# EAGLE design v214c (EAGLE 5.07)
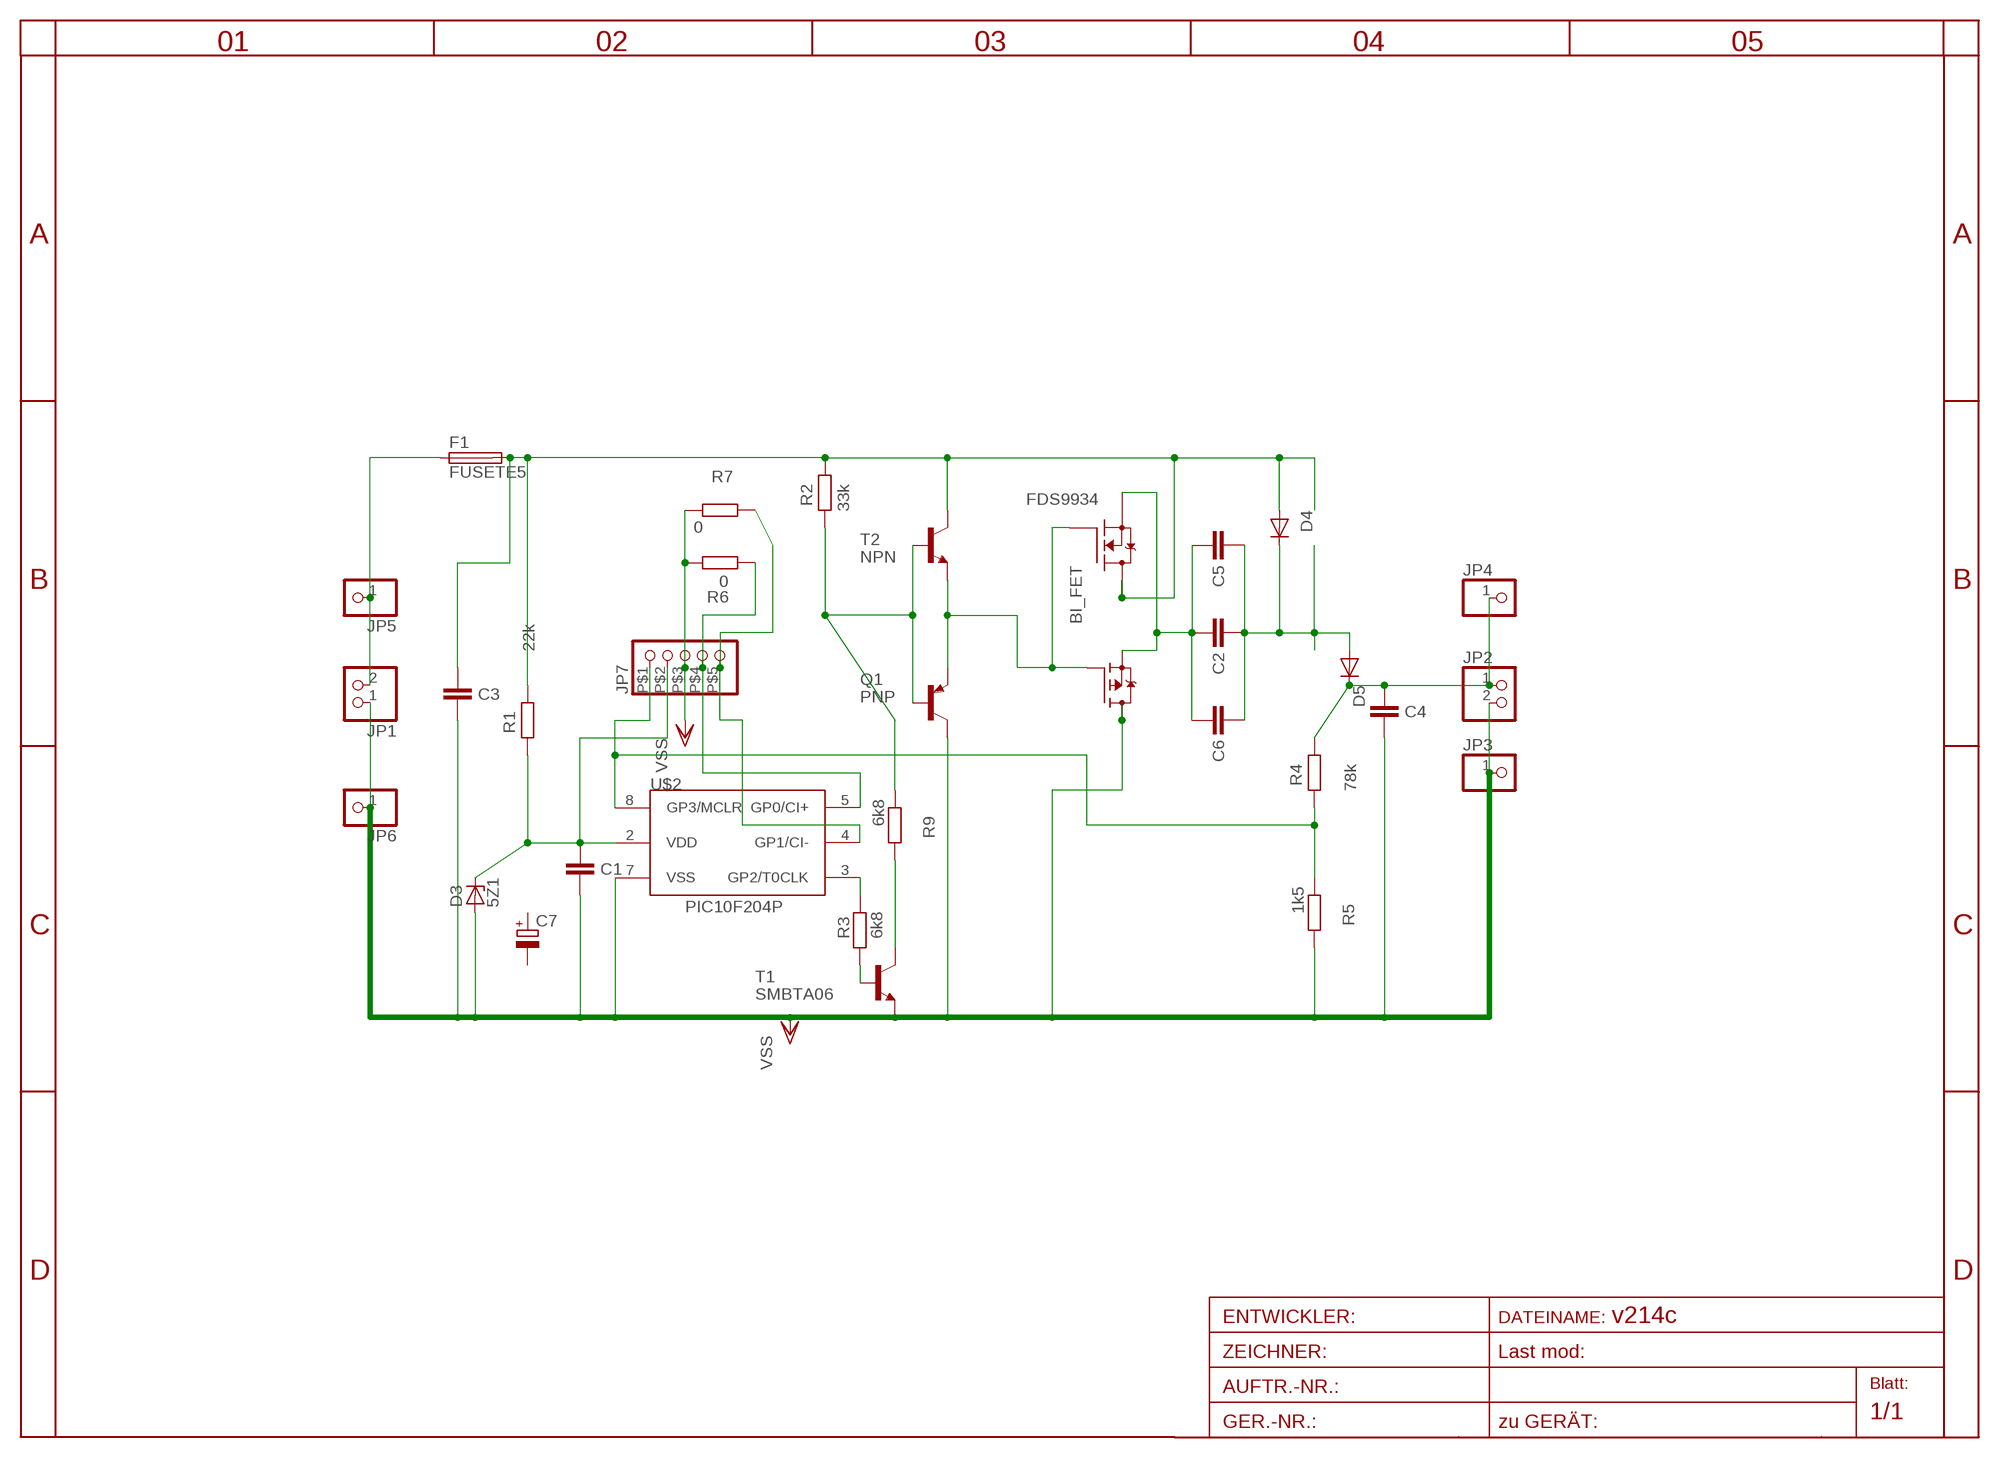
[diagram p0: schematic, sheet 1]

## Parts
BI_FET  FDS9934  [SO-8]
C1  1u  C-EUC1206  [C1206]
C2  10n  C-EUC1206  [C1206]
C3  10n  C-EU050-075X075  [C050-075X075]
C4  10n  C-EU050-075X075  [C050-075X075]
C5  10n  C-EU050-025X075  [C050-025X075]
C6  10n  C-EUC1206  [C1206]
C7  CPOL-EUSMCA  [SMC_A]
D3  5Z1  ZENER-DIODESOD80C  [SOD80C]
D4  DIODE-SMC  [SMC]
D5  DIODE-SMC  [SMC]
F1  FUSETE5  [TE5]
JP1  PINHD-1X2  [1X02X05]
JP2  PINHD-1X2  [1X02X05]
JP3  PINHD-1X11MM6  [1X1MM8]
JP4  PINHD-1X11MM6  [1X1MM8]
JP5  PINHD-1X11MM6  [1X1MM8]
JP6  PINHD-1X11MM6  [1X1MM8]
JP7  PINHD-1X5  [1X05SMD]
Q1  PNP  BC857ASMD  [SOT23-BEC]
R1  22k  R-EU_R1206  [R1206]
R2  33k  R-EU_R1206  [R1206]
R3  6k8  R-EU_R1206  [R1206]
R4  78k  R-EU_R2010  [R2010]
R5  1k5  R-EU_R1206  [R1206]
R6  0  R-EU_R0402  [R0402]
R7  0  R-EU_R0402  [R0402]
R9  6k8  R-EU_R1206  [R1206]
T1  SMBTA06  BC846  [SOT23]
T2  NPN  BC846  [SOT23]
U$2  PIC10F204P  [DIL8]

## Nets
GG: BI_FET.2(Q1G) BI_FET.4(Q2G) Q1.E T2.2(E)
N$1: C1.2 D3.C JP7.P$2 R1.2 U$2.2(VDD)
N$2: R9.2 T1.3(C)
N$3: R3.2 U$2.3(GP2/T0CLK)
N$4: R3.1 T1.1(B)
N$5: JP7.P$1 R4.2 R5.1 U$2.8(GP3/MCLR)
N$6: Q1.B R2.2 R9.1 T2.1(B)
N$7: JP7.P$4 R6.1 U$2.5(GP0/CI+)
N$8: JP7.P$5 R7.2 U$2.4(GP1/CI-)
SS: BI_FET.1(Q1S) BI_FET.3(Q2S) C2.1 C5.1 C6.1
V+IN: F1.1 JP1.2 JP5.1
VFUSE: BI_FET.7(Q1D2) BI_FET.8(Q1D1) C3.2 D4.A F1.2 R1.1 R2.1 T2.3(C)
VMID: C2.2 C5.2 C6.2 D4.C D5.A
VOUT: C4.2 D5.C JP2.1 JP4.1 R4.1
VSS: BI_FET.5(Q2D2) BI_FET.6(Q2D) C1.1 C3.1 C4.1 D3.A JP1.1 JP2.2 JP3.1 JP6.1 JP7.P$3 Q1.C R5.2 R6.2 R7.1 T1.2(E) U$2.7(VSS)
Unconnected: C7.+ C7.-

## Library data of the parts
BI_FET = transistor-fet:FDS9934
C1-C6 = rcl-2:C-EU: CAPACITOR, European symbol
C7 = rcl:CPOL-EU: POLARIZED CAPACITOR, European symbol
D3 = diode-1:ZENER-DIODE: Z-Diode
D4 D5 = diode-1:DIODE-: DIODE
F1 = fuse:FUSE: Fuse
JP1 JP2 = pinhead:PINHD-1X2: PIN HEADER
JP3-JP6 = pinhead:PINHD-1X1: PIN HEADER
JP7 = pinhead:PINHD-1X5: PIN HEADER
Q1 = transistor-pnp:BC857*: PNP Transistror
R1-R7 R9 = rcl-2:R-EU_: RESISTOR, European symbol
T1 T2 = transistor:BC846: NPN TRANSISTOR
U$2 = microchip-5:PIC10F2*: uPC nW 0,25/0,5k Program Flash memory Comparator

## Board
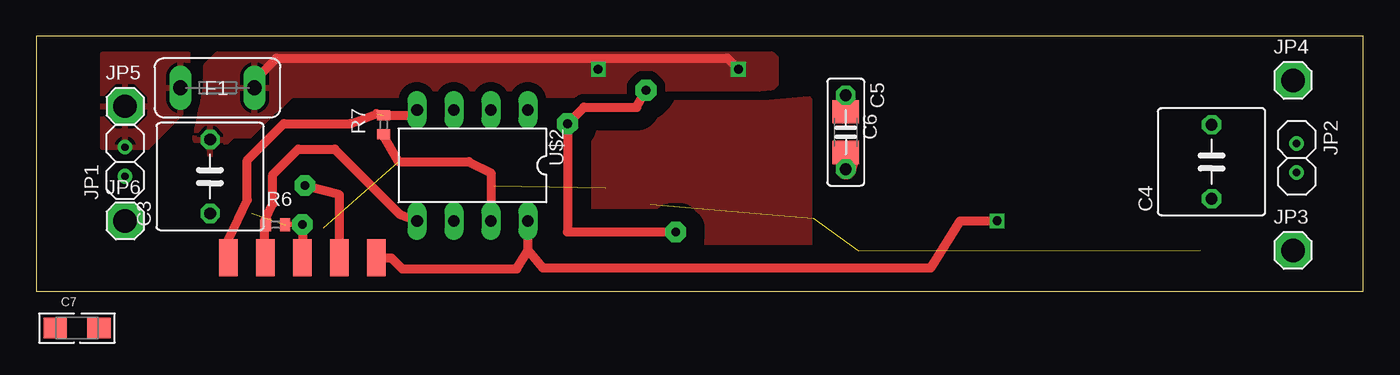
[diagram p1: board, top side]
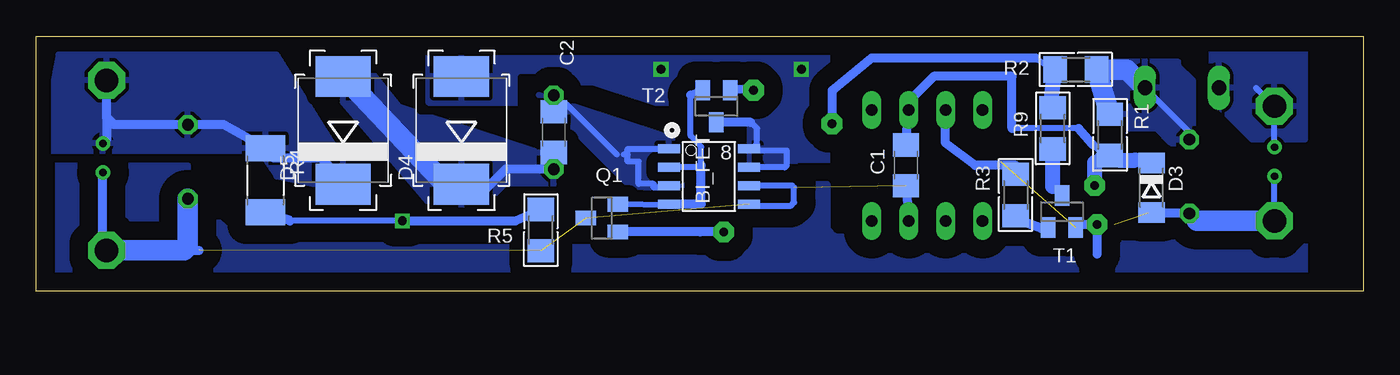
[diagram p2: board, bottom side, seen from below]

Size 91.19 x 17.5 mm. Coordinates in mm from the lower left corner, seen from the top.
Outline: 0,0 91.19,0 91.19,17.5 0,17.5 0,0
Copper layers (1*16): Top 0.035mm / dielectric 1.5mm / Bottom 0.035mm
Design rules "default": minimum track width 10mil, minimum drill 24mil, track to track 8mil, track to pad 8mil, pad to pad 8mil, via to via 8mil, smd to smd 8mil, copper to edge 40mil, drill to drill 8mil, minimum pad ring 10mil, minimum via ring 8mil, stop-mask expansion 4mil, vias tented up to drill 0mil, thermal gap 10mil

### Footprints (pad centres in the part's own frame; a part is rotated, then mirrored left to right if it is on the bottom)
SO-8 = smd 1.524 x 0.61: 1 -2.743,1.905; 2 -2.743,0.635; 3 -2.743,-0.635; 4 -2.743,-1.905; 5 2.743,-1.905; 6 2.743,-0.635; 7 2.743,0.635; 8 2.743,1.905
C1206 = smd 1.6 x 1.8: 1 -1.4,0; 2 1.4,0
C050-075X075 = drill 0.813 octagon: 1 -2.54,0; 2 2.54,0
C050-025X075 = drill 0.813 octagon: 1 -2.54,0; 2 2.54,0
SMC_A = smd 1.6 x 1.4: + -1.5,0; - 1.5,0
SOD80C = smd 1.4 x 1.8: A 1.7,0; C -1.7,0
SMC = smd 2.8 x 3.8: A 3.7,0; C -3.7,0
TE5 = drill 1.016 long: 1 -2.54,0; 2 2.54,0
1X02X05 = drill 0.5 pad 0.813 round: 1 -1,0; 2 1,0
1X1MM8 = drill 1.6 pad 2.54 octagon: 1 0,0
1X05SMD = smd 1.27 x 2.54: P$1 -5.08,0; P$2 -2.54,0; P$3 0,0; P$4 2.54,0; P$5 5.08,0
SOT23-BEC = smd 1 x 1.4: B -0.95,-1.1; C 0,1.1; E 0.95,-1.1
R1206 = smd 1.6 x 1.803: 1 -1.422,0; 2 1.422,0
R2010 = smd 1.8 x 2.7: 1 -2.2,0; 2 2.2,0
R0402 = smd 0.7 x 0.9: 1 -0.65,0; 2 0.65,0
SOT23 = smd 1 x 1.4: 1 -0.95,-1.1; 2 0.95,-1.1; 3 0,1.1
DIL8 = drill 0.8 long: 1 -3.81,-3.81; 2 -1.27,-3.81; 3 1.27,-3.81; 4 3.81,-3.81; 5 3.81,3.81; 6 1.27,3.81; 7 -1.27,3.81; 8 -3.81,3.81

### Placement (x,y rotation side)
BI_FET  44.96,7.87 0 bottom
C1  31.43,8.64 90 bottom
C2  55.63,10.92 270 bottom
C3  11.94,7.87 90 top
C4  80.77,8.89 90 top
C5  55.63,10.92 270 top
C6  55.63,10.92 270 top
C7  2.79,-2.54 0 top
D3  14.54,7.11 270 bottom
D4  61.98,11.05 90 bottom
D5  70.1,11.05 90 bottom
F1  12.45,13.97 0 top
JP1  6.1,8.89 90 top
JP2  86.61,9.14 270 top
JP3  86.36,2.79 0 top
JP4  86.36,14.48 0 top
JP5  6.1,12.7 0 top
JP6  6.1,4.83 0 top
JP7  18.29,2.29 180 top
Q1  52.32,5.02 90 bottom
R1  17.4,10.73 270 bottom
R2  19.75,15.22 180 bottom
R3  23.88,6.6 90 bottom
R4  75.44,7.62 270 bottom
R5  56.52,4.19 270 bottom
R6  16.45,4.57 0 top
R7  23.88,11.43 90 top
R9  21.34,11.18 270 bottom
T1  20.7,5.46 0 bottom
T2  44.45,12.7 180 bottom
U$2  29.97,8.64 180 top

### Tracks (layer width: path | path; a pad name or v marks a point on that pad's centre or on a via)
GG
  Bottom 0.406: BI_FET.2 45.59,8.51 45.5,8.64 45.5,9.91 46.23,10.67 46.23,13.46 | Q1.E 47.77,5.9 BI_FET.4
  Bottom 0.61: 46.23,13.46 T2.2 | BI_FET.4 45.5,5.97 45.5,8.64
N$1  (via drill 0.6 pad 1.42)
  Top 0.61: JP7.P$2 20.83,6.6 v18.45,7.25
  Bottom 0.406: 31.43,10.6 C1.2 | 15.67,9 D3.C | 31.25,13 U$2.2 | 18.61,10.08 17.97,9.51 R1.2 16.81,9 | 19.56,11.18 24.13,11.18
  Bottom 0.61: U$2.2 31.43,10.6 | 31.25,13 29.5,14.75 24.13,14.75 24.13,11.18 | 18.61,10.08 19.56,11.18 | 18.45,8.83 17.97,9.51
  Bottom 1.016: 16.81,9 15.67,9 | v18.45,7.25 18.45,8.83
N$2
  Bottom 0.406: T1.3 21.34,7.2
  Bottom 1.016: 21.34,7.2 R9.2
N$3
  Bottom 0.406: R3.2 23.62,7.87 23.88,8.64
  Bottom 0.61: 23.88,8.64 26.67,8.64 28.7,10.16 U$2.3
N$4
  Bottom 0.406: R3.1 23.47,4.67 23.62,4.83 | T1.1 22.12,4.32
  Bottom 0.61: 22.12,4.32 23.62,4.83
N$5  (via drill 0.6)
  Top 0.61: JP7.P$1 24.38,2.29 25.15,1.52 33.02,1.52 33.78,2.79 | 33.78,2.79 U$2.8 | v66.04,4.83 63.5,4.83 61.47,1.59 34.8,1.59 33.78,2.79
  Bottom 0.406: v66.04,4.83 73.75,4.83
  Bottom 0.61: R5.1 58.27,4.83 v66.04,4.83 | 73.75,4.83 R4.2
N$6  (via drill 0.6 pad 1.42)
  Top 0.61: v43.94,4.06 36.5,4.06 v36.5,11.5 37.64,12.64 38.27,12.63 41.26,12.63 v41.9,13.8
  Bottom 0.406: R2.2 21.76,15.49 22.52,16 | R9.1 21.59,12.19 21.5,12.61
  Bottom 0.61: v36.5,11.5 36.5,13.78 33.78,16 22.52,16 | T2.1 42.04,13.91 v41.9,13.8 | v43.94,4.06 45.57,4.06 Q1.B
  Bottom 1.016: 21.5,12.61 R2.2
N$7
  Top 0.61: JP7.P$4 15.68,3.56 15.68,4.57 | 15.68,4.57 15.68,4.83 16.25,6 16.25,8 18,9.75 20.5,9.75 25,5.25 U$2.5 | 15.68,4.57 R6.1
N$8  (1 unrouted)
  Top 0.406: 25.8,12.08 U$2.4
  Top 0.61: JP7.P$5 13.21,3.56 14.5,6.25 14.5,9 17,11.5 21.59,11.5 23.37,12.19 | R7.2 25.8,12.08
N$9
  pour Top (isolate 1.27): 37.85,12.95 50.04,12.95 53.09,13.21 53.09,2.29 37.85,2.29
SS
  Top 0.406: C6.1 55.88,13.21 C5.1
  Bottom 0.406: C5.1 56.13,12.96 C6.1 54.74,12.83 51.31,9.4 | BI_FET.1 50.55,9.78 50.55,9.4 | 50.55,9.4 50.55,8.89 49.78,8.89 49.78,7.37 48.77,7.37 48.77,7.11 47.7,7.11 BI_FET.3 | 50.55,9.4 50.8,9.4
  pour Bottom (isolate 0.813, rank 2): 56.64,13.46 50.29,7.11 46.74,7.11 47.24,10.41
V+IN
  Bottom 0.406: 7.37,13.97 JP5.1 JP1.2
  pour Bottom (isolate 0.61, rank 3): 10.41,13.72 10.41,16.76 4,16.76 4,10.41 7.62,10.41 10.16,12.95
  pour Top (isolate 0.61, rank 3): 10.41,13.21 10.41,16.26 4.57,16.26 4.57,9.91 7.62,9.91 10.16,12.45
V-
  pour Bottom (isolate 1.27): 4,0.51 89.92,0.51 89.92,8.64 80.77,8.64 80.77,6.6 76.96,3.3 57.4,3.3 54.86,5.33 53.34,5.33 51.31,3.3 43.43,3.05 43.43,7.37 36.83,7.37 36.83,4.32 36.32,3.81 15.75,3.3 12.45,6.1 4,6.1
VFUSE  (via drill 0.6)
  Top 0.61: F1.2 14.99,14.48 16.51,16 47.5,16 v48.26,15.24
  Bottom 0.406: C3.2 11.94,10.92 F1.2 | BI_FET.7 39.75,8.51 39.62,8.64 39.62,9.65 41.83,9.65 BI_FET.8 41.66,10.08 41.66,11.18 42.08,11.6
  Bottom 0.61: 42.08,11.6 T2.3
  Bottom 1.422: R1.1 17.55,12.57 R2.1 16.24,15.22 F1.2
  other vias: 38.61,15.24
  pour Bottom (isolate 1.27, rank 3): 64.01,17.02 64.26,17.02 64.26,12.95 43.18,12.95 42.16,12.45 42.16,8.26 36.83,8.26 36.83,16.76
  pour Bottom (isolate 0.61, rank 3): 12.7,15.75 18.29,15.75 18.29,13.21 16.26,11.18 14.22,11.18 13.21,10.16 11.94,10.16 11.68,10.41 11.68,14.48 12.7,15.49
  pour Top (isolate 0.61, rank 3): 11.68,13.97 11.68,15.49 12.45,16.26 50.55,16.26 50.8,16 50.8,14.22 50.04,13.46 17.53,13.46 14.73,10.67 13.46,10.67 12.19,9.4 11.94,9.4 10.92,10.41
VMID
  Top 1.422: C6.2 55.75,8.76 C5.2
  Bottom 0.406: C5.2 56.13,9.9 C6.2
  Bottom 0.61: D4.C 60.34,6.97 58.93,8.38 C5.2
  Bottom 1.422: D4.C 62.7,6.97 D5.A
  pour Bottom (isolate 0.61, rank 4): 55.37,9.14 55.37,7.37 58.93,7.37 60.45,5.84 64.01,5.84 71.63,14.73 68.33,15.24 66.29,12.7
VOUT
  Bottom 0.61: D5.C 70.1,7.62 71.63,9.14 74.84,9.14 R4.1 78.32,11.43 C4.2 85.85,11.43 86.36,11.94 | 86.36,11.94 86.36,10.4 JP2.1 | 86.36,11.94 JP4.1
  pour Bottom (isolate 0.61, rank 3): 74.68,16.26 89.66,16.26 90.93,9.65 76.96,9.65 75.69,9.4 74.68,7.87 68.58,6.6
VSS  (via drill 0.6 pad 1.42)  (6 unrouted)
  Top 0.406: 23.88,10.67 R7.1 | R6.2 18.43,4.71 v18.29,4.57
  Top 0.61: v18.29,4.57 JP7.P$3 | 23.88,10.67 24.89,8.89 29.72,8.89 31.24,8.13 U$2.7
  Bottom 0.406: 11.43,4.83 C3.1 | JP6.1 JP1.1 | U$2.7 31.24,5.71 | BI_FET.6 39.24,7.24 39.12,7.11 39.12,6.1 39.37,5.84 41.83,5.84 BI_FET.5
  Bottom 0.61: 31.24,5.71 C1.1 | T1.2 19.54,4.57 v18.29,4.57 18.29,2.54 | C3.1 14.78,5.33 D3.A | 80.01,2.79 81.03,2.79 80.77,3.05 | JP2.2 86.61,3.05 JP3.1
  Bottom 1.422: 81.03,2.79 JP3.1 | 80.77,3.05 C4.1 | JP6.1 11.43,4.83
